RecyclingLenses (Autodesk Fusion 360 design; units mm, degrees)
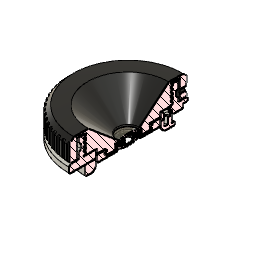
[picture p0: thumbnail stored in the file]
parameter "emount_flange_distance" = 18
parameter "lens_focal_length" = 30
parameter "single_lens_distance" = 12 (= "lens_focal_length - emount_flange_distance")
parameter "double_lens_distance" = 1.6
parameter "thread_clearing" = 0.1 comment "increase value to make more space between threads"
parameter "lens_diameter" = 13.4 (= "13 mm + 0.4 mm")
parameter "lens_height" = 0.8 (= "1 mm - 0.2 mm")
sketch "Sketch1" plane through (0, 0, 0) normal (0, 0, 1) x axis (1, 0, 0)
  line L1 (0, 0) -> (-5.9612, -25.8208)
  line L2 (23.25, 0) -> (0, 0)
  line L3 (-23.25, 0) -> (0, 0)
  line L4 (0, 29.5) -> (0, 23.25)
  line L5 (13.0012, 19.2751) -> (12.1764, 18.0523)
  line L6 (17.004, -15.8565) -> (0, 0)
  line L7 (13.0012, 19.2751) -> (0, 0)
  line L8 (0, 23.25) -> (0, 0)
  line L9 (-16.1304, -16.7443) -> (0, 0)
  line L10 (-7.952, 21.8479) -> (0, 0)
  line L11 (17.004, -15.8565) -> (15.9252, -14.8505)
  line L12 (-14.6317, -18.0686) -> (0, 0)
  line L13 (0, -21.775) -> (0, 0)
  line L14 (-23.1934, 1.6218) -> (0, 0)
  line L15 (-23.1934, 1.6218) -> (-21.722, 1.5189)
  line L16 (-7.952, 21.8479) -> (-7.4475, 20.4618)
  line L17 (29.5, 0) -> (23.25, 0)
  line L18 (-4.7282, -25.5923) -> (-4.9532, -26.5667)
  line L19 (-14.6317, -18.0686) -> (-13.7035, -16.9224)
  line L20 (-5.8487, -25.3336) -> (-6.0737, -26.308)
  line L21 (-15.1071, -15.682) -> (-16.1304, -16.7443)
  line L22 (-7.1942, -26.0493) -> (-6.9693, -25.0749)
  line L23 (23.2358, 0.8114) -> (0, 0)
  line L24 (23.2358, 0.8114) -> (21.7617, 0.7599)
  line L25 (-0.725, -21.7629) -> (-0.725, -16.4841)
  line L26 (0.725, -21.7629) -> (0.725, -16.4841)
  arc A1 centre (0, 0) radius 23.25 clockwise from (-7.952, 21.8479) to (13.0012, 19.2751)
  circle C1 centre (0, 19) radius 0.95
  arc A2 centre (0, 0) radius 23.25 clockwise from (-14.6317, -18.0686) to (-23.1934, 1.6218)
  arc A3 centre (-6.0737, -26.308) radius 1.15 clockwise from (-4.9532, -26.5667) to (-7.1942, -26.0493)
  circle C2 centre (0, 0) radius 23.25
  circle C3 centre (0, 0) radius 21.775
  circle C4 centre (-16.4545, -9.5) radius 0.95
  circle C5 centre (0, 0) radius 16.5
  circle C6 centre (16.4545, -9.5) radius 0.95
  arc A4 centre (-5.8487, -25.3336) radius 1.15 clockwise from (-6.9693, -25.0749) to (-4.7282, -25.5923)
  arc A5 centre (0, 0) radius 23.25 clockwise from (23.2358, 0.8114) to (17.004, -15.8565)
  circle C7 centre (0, 19) radius 1.9
  circle C8 centre (-16.4545, -9.5) radius 1.9
  circle C9 centre (16.4545, -9.5) radius 1.9
  point P11 (0, 0)
  point P21 (0, 0)
  point P12 (0, 0)
  point P17 (0, 0)
  point P16 (-23.1934, 1.6218)
  point P28 (0, 0)
  point P29 (0, 0)
  point P30 (17.004, -15.8565)
  point P38 (0, 0)
  point P39 (13.0012, 19.2751)
  point P6 (-7.952, 21.8479)
  point P7 (0, 0)
  point P43 (23.25, 0)
  point P44 (-21.722, 1.5189)
  point P41 (15.9252, -14.8505)
  point P8 (-23.25, 0)
  point P22 (0, 0)
  point P23 (-14.6317, -18.0686)
  point P24 (-13.7035, -16.9224)
  point P33 (0, 0)
  point P46 (0, 0)
  point P32 (0, 23.25)
  point P25 (12.1764, 18.0523)
  point P45 (-7.4475, 20.4618)
  point P26 (0, 0)
  point P27 (-16.1304, -16.7443)
  point P18 (-15.1071, -15.682)
  point P13 (0, -21.775)
  point P42 (-5.8487, -25.3336)
  point P14 (-5.9612, -25.8208)
  point P35 (-5.9612, -25.8208)
  point P40 (0, 0)
  point P31 (0, 0)
  point P36 (0, 19)
  point P1 (0, 0)
  point P37 (0, 0)
  point P47 (0, 0)
  point P48 (23.2358, 0.8114)
  point P49 (21.7617, 0.7599)
  point P15 (0, 0)
  point P50 (0, 0)
  point P51 (23.25, 0)
  point P52 (16.5, 0)
  point P53 (21.775, 0)
  point P54 (-0.725, -16.4841)
  point P55 (-0.725, -21.7629)
  point P57 (0.725, -21.7629)
  point P56 (0.725, -16.4841)
  point P34 (-6.0737, -26.308)
  coincident P11 P21
  coincident P12 P21
  coincident P17 P21
  coincident P16 C2
  coincident P12 P28
  coincident P11 P29
  coincident P30 C2
  coincident P21 P38
  coincident P39 C2
  coincident P6 C2
  coincident P7 P12
  horizontal L2
  coincident P43 C2
  coincident P44 C3
  coincident P44 L14
  coincident P41 C3
  coincident P41 L6
  horizontal L3
  coincident P8 C2
  coincident P11 P22
  coincident P23 C2
  coincident P24 L12
  coincident P24 C3
  coincident P33 P46
  coincident P32 A1
  coincident P25 C3
  coincident P25 L7
  coincident P45 C3
  coincident P45 L10
  vertical L8
  coincident P12 P26
  coincident P27 A2
  coincident P18 L9
  coincident P18 C3
  coincident P13 C3
  vertical L13
  tangent L18 A4
  tangent L22 A4
  parallel L18 L22
  tangent A3 L22
  tangent A3 L18
  coincident P42 L1
  parallel L1 L20
  coincident P14 P35
  midpoint P35 L20
  coincident P28 P40
  coincident P21 P31
  concentric A1 C5
  coincident P36 L8
  parallel L2 L17
  parallel L4 L8
  coincident P1 P37
  coincident P12 P47
  coincident C2 P48
  coincident C3 P49
  coincident L23 P49
  coincident P15 P50
  coincident P21 P50
  coincident P43 P51
  coincident C5 P52
  coincident L2 P52
  coincident C3 P53
  coincident L2 P53
  coincident C5 P54
  coincident C3 P55
  vertical L25
  coincident C3 P57
  parallel L25 L26
  coincident C5 P56
  concentric C1 C7
  dimension "d214" diameter C3 = 43.55
  dimension "d215" diameter C2 = 46.5 (= "46.20 mm + 0.3 mm")
  dimension "d216" angle L3 L14 = 4
  dimension "d217" angle L3 L12 = 51
  dimension "d219" angle L2 L6 = 43
  dimension "d220" angle L7 L8 = 34
  dimension "d221" angle L8 L10 = 20
  dimension "d223" angle L12 L14 = 55
  dimension "d224" angle L7 L10 = 54
  dimension "d225" distance P23 P27 = 2
  dimension "d226" angle L1 L13 = 13
  dimension "d227" distance P14 P15 = 26.5
  dimension "d228" distance P34 P42 = 1
  dimension "d229" distance L18 L22 = 2.3
  dimension "d231" distance P36 P37 = 19
  dimension "d232" diameter C1 = 1.9
  dimension "d239" angle L2 L23 = 2
  dimension "d285" distance L25 L26 = 1.45 (= "1.2 mm + 0.25 mm")
  dimension "d349" diameter C7 = 3.8
  dimension "d471" diameter C5 = 33
  dimension "d213" C-Pattern1-Angle = 360
sketch "Sketch2" plane through (0, 0, 0) normal (0, 1, 0) x axis (1, 0, 0)
  line L1 (23.25, -1.6) -> (23.25, 0)
  line L2 (21.775, -1.6) -> (23.25, -1.6)
  line L3 (21.775, -5.2) -> (21.775, -1.6)
  line L4 (18, 0) -> (23.25, 0)
  line L5 (16.5, -5.2) -> (16.5, -1.5)
  line L6 (21.775, -5.2) -> (16.5, -5.2)
  line L7 (21.775, -7.2) -> (21.775, -5.2)
  line L8 (20.775, -7.2) -> (21.775, -7.2)
  line L9 (18.775, -5.2) -> (20.775, -7.2)
  line L10 (0, 0) -> (16.5, 0)
  line L11 (16.5, -1.5) -> (18, 0)
  line L12 (18, 0) -> (16.5, 0)
  line L13 (21.775, 0) -> (21.775, -1.6)
  point P11 (18.775, -5.2)
  point P13 (23.25, 0)
  point P15 (21.775, 0)
  point P1 (0, 0)
  point P12 (0, 0)
  point P2 (23.25, 0)
  point P6 (16.5, 0)
  point P14 (16.5, 0)
  point P17 (21.775, 0)
  point P3 (23.25, -1.6)
  point P7 (16.5, -1.5)
  point P16 (18, 0)
  point P5 (21.775, -5.2)
  point P9 (21.775, -7.2)
  point P10 (20.775, -7.2)
  perpendicular L1 L2
  perpendicular L1 L4
  perpendicular L4 L5
  perpendicular L3 L6
  perpendicular L6 L7
  perpendicular L7 L8
  coincident L6 P11
  parallel L4 L10
  perpendicular L2 L3
  horizontal L4
  coincident L1 P13
  coincident L3 P15
  coincident P1 P12
  coincident P2 P13
  coincident P6 L5
  coincident L5 P14
  coincident P15 P17
  dimension "d240" distance P2 P3 = 1.6
  dimension "d243" distance P2 L6 = 5.2
  dimension "d244" angle L11 L12 = 45
  dimension "d245" distance P7 P16 = 1.5
  dimension "d246" angle L6 L9 = 45
  dimension "d247" distance P5 P9 = 2
  dimension "d260" distance P9 P10 = 1
  dimension "d261" distance P9 P11 = 3
revolve "Revolve1" sketch "Sketch2" AlongAngle 360 bodies "EMountFlange"
extrude "Extrude1" add sketch "Sketch1" profile of A1 L5 A2 L11 C3 L15 L16 L19 L21 A4 L24 A5 to an object
fillet "Fillet1" radius 2
extrude "Extrude2" add sketch "Sketch1" profile of A2 C3 L19 L21 to an object offset -0.2
chamfer "Chamfer1" distance 0.4 distance 0.8
sketch "Sketch1" plane through (0, 0, 0) normal (0, 1, 0) x axis (1, 0, 0)
  line L1 (18.6336, 0) -> (16.5, 0)
  line L2 (20.9336, -2.3) -> (18.6336, 0)
  line L3 (22.075, -2.3) -> (20.9336, -2.3)
  line L4 (22.075, 0) -> (22.075, -2.3)
  line L5 (30, 0) -> (22.075, 0)
  line L6 (22.5, -13.5) -> (25, -13.5)
  line L7 (22.5, -4) -> (22.5, -13.5)
  line L8 (16.5, -4) -> (22.5, -4)
  line L9 (16.5, 0) -> (16.5, -4)
  line L10 (30, 0) -> (0, 0)
  line L11 (21.775, -2) -> (21.775, 0)
  line L12 (20.775, -2) -> (21.775, -2)
  line L13 (18.775, 0) -> (20.775, -2)
  line L14 (30, -4) -> (30, 0)
  line L15 (25, -4) -> (30, -4)
  line L16 (25, -13.5) -> (25, -4)
  point P1 (0, 0)
  point P11 (0, 0)
  point P2 (16.5, 0)
  point P12 (21.775, 0)
  point P15 (18.775, 0)
  point P18 (25, -13.5)
  point P5 (22.075, -2.3)
  point P13 (21.775, -2)
  point P14 (20.775, -2)
  point P7 (30, 0)
  point P8 (22.5, -13.5)
  point P10 (16.5, -4)
  point P16 (30, -4)
  horizontal L1
  parallel L1 L3
  perpendicular L3 L4
  perpendicular L4 L5
  perpendicular L3 L7
  perpendicular L7 L8
  perpendicular L1 L9
  coincident P1 P11
  coincident P2 L10
  coincident L10 P12
  perpendicular L10 L11
  perpendicular L11 L12
  coincident L10 P15
  parallel L2 L13
  perpendicular L10 L14
  perpendicular L14 L15
  coincident L6 P18
  perpendicular L6 L16
  coincident P1 L5
  dimension "d262" distance P1 P12 = 21.775 (= "( 43.55 / 2 ) * 1 mm")
  dimension "d263" distance P5 P13 = 0.3
  dimension "d264" angle L10 L13 = 45
  dimension "d265" distance L2 L13 = 0.1
  dimension "d266" distance P12 P13 = 2
  dimension "d267" distance P5 P13 = 0.3
  dimension "d268" distance P13 P14 = 1
  dimension "d269" distance P1 P7 = 30 (= "( 60 / 2 ) * 1 mm")
  dimension "d271" distance P1 P8 = 22.5 (= "( 45 / 2 ) * 1 mm")
  dimension "d272" distance P2 P10 = 4
  dimension "d414" distance P7 P16 = 4
  dimension "d415" distance L5 L6 = 13.5
  dimension "d416" distance P1 P18 = 25 (= "( 50 / 2 ) * 1 mm")
  dimension "d472" distance P1 P10 = 16.5 (= "( 33 / 2 ) * 1 mm")
sketch "Sketch2" plane through (0, 0, 0) normal (0, 0, 1) x axis (1, 0, 0)
  line L1 (0, -26.5) -> (0, 0)
  line L2 (-5.9612, -25.8208) -> (0, 0)
  line L3 (-4.4284, -25.405) -> (-4.7658, -26.8665)
  line L4 (-7.494, -26.2367) -> (-7.1566, -24.7751)
  line L5 (-5.7925, -25.09) -> (-6.1299, -26.5516)
  line L6 (-0.6, -22.0668) -> (-0.6, -18.6239)
  line L7 (0.6, -22.0668) -> (0.6, -18.6239)
  line L8 (0, 30) -> (0, 0)
  circle C1 centre (0, 0) radius 26.5
  arc A1 centre (-5.7925, -25.09) radius 1.4 clockwise from (-7.1566, -24.7751) to (-4.4284, -25.405)
  arc A2 centre (-6.1299, -26.5516) radius 1.4 clockwise from (-4.7658, -26.8665) to (-7.494, -26.2367)
  circle C2 centre (0, 0) radius 22.075
  circle C3 centre (0, 0) radius 18.6336
  arc A3 centre (0, 0) radius 18.6336 clockwise from (0.6, -18.6239) to (-0.6, -18.6239)
  arc A4 centre (0, 0) radius 22.075 clockwise from (0.6, -22.0668) to (-0.6, -22.0668)
  circle C4 centre (0, 0) radius 30
  circle C5 centre (0, 30) radius 2.5
  circle C6 centre (0, 19) radius 1.15
  circle C7 centre (-16.4545, -9.5) radius 1.15
  circle C8 centre (16.4545, -9.5) radius 1.15
  circle C9 centre (0, 19) radius 2.15
  circle C10 centre (-16.4545, -9.5) radius 2.15
  circle C11 centre (16.4545, -9.5) radius 2.15
  point P1 (0, 0)
  point P2 (0, 0)
  point P4 (0, 0)
  point P3 (0, -26.5)
  point P5 (0, 0)
  point P6 (-5.9612, -25.8208)
  point P12 (-5.7925, -25.09)
  point P13 (-5.9612, -25.8208)
  point P14 (0, 0)
  point P16 (-0.6, -18.6239)
  point P17 (-0.6, -22.0668)
  point P18 (0.6, -18.6239)
  point P19 (0.6, -22.0668)
  point P20 (0, 0)
  point P21 (0, 0)
  point P22 (18.6336, 0)
  point P23 (22.075, 0)
  point P24 (30, 0)
  point P26 (0, 0)
  point P27 (0, 30)
  point P28 (0, 30)
  point P29 (0, 19)
  point P11 (-6.1299, -26.5516)
  point P7 (-4.7658, -26.8665)
  point P10 (-7.494, -26.2367)
  point P25 (0, 0)
  coincident P1 P2
  vertical L1
  coincident P1 P4
  coincident P3 C1
  coincident P4 P5
  coincident C1 P6
  tangent L3 A1
  tangent A1 L4
  parallel L3 L4
  tangent L4 A2
  tangent L3 A2
  coincident L2 P12
  parallel L2 L5
  coincident P6 P13
  midpoint L5 P13
  coincident P1 P14
  concentric C2 C3
  coincident C3 P16
  coincident C2 P17
  parallel L1 L6
  coincident C3 P18
  coincident C2 P19
  parallel L1 L7
  coincident P4 P20
  coincident P20 P21
  symmetric L1 L6 L7
  coincident C3 P22
  coincident C2 P23
  concentric A3 C4
  coincident P24 C4
  coincident P1 P26
  coincident C4 P27
  vertical L8
  coincident P27 P28
  coincident L8 P29
  concentric C6 C9
  dimension "d279" distance P5 P6 = 26.5
  dimension "d280" angle L1 L2 = 13
  dimension "d281" distance P11 P12 = 1.5
  dimension "d282" distance P7 P10 = 2.8
  dimension "d290" distance L6 L7 = 1.2
  dimension "d302" diameter C5 = 5
  dimension "d340" diameter C6 = 2.3
  dimension "d343" distance P25 P29 = 19
  dimension "d354" diameter C9 = 4.3
  dimension "d342" C-Pattern1-Angle = 360
revolve "Revolve1" sketch "Sketch1" AlongAngle 360
extrude "Extrude1" cut sketch "Sketch2" profile of L3 A1 L4 A2 along normal blind 2
extrude "Extrude2" add sketch "Sketch2" profile of L6 L7 A3 A4 to an object
joint "Assemble1" alignAngle 0 alignOffsetX 0 alignOffsetY 0 alignOffsetZ 0
extrude "Extrude3" sketch "Sketch1" profile of C3 C5 L25 L26 to an object
chamfer "Chamfer2" distance 0.4
extrude "Extrude3" cut sketch "Sketch2" profile of C5 along normal blind 2
extrude "Extrude4" cut sketch "Sketch2" profile of C6 C7 C8 to an object
chamfer "Chamfer1" distance 0.25
chamfer "Chamfer2" distance 0.3
thread "Thread1"
chamfer "Chamfer4" distance 0.2
sketch "Sketch1" plane through (0, 0, 0) normal (0, 1, 0) x axis (1, 0, 0)
  line L1 (30, -15) -> (5.5, -15)
  line L2 (30, -4.3) -> (30, -15)
  line L3 (26, -13.8) -> (26, -4.3)
  line L4 (22.5, -13.8) -> (26, -13.8)
  line L5 (22.5, -4) -> (22.5, -13.8)
  line L6 (16.5, -4) -> (22.5, -4)
  line L7 (16.5, -13.8) -> (16.5, -4)
  line L8 (10, -13.8) -> (16.5, -13.8)
  line L9 (10, -11.2) -> (10, -13.8)
  line L10 (5.5, -15) -> (5.5, -12)
  line L11 (7.1782, -15) -> (5.5, -13)
  line L12 (16, -13.4) -> (10, -13.4)
  line L13 (16, -9.4) -> (16, -13.4)
  line L14 (27.5, -15) -> (30, -12.5)
  line L15 (6.7, -12) -> (5.5, -12)
  line L16 (6.7, -11.2) -> (6.7, -12)
  line L17 (10, -11.2) -> (6.7, -11.2)
  line L18 (1.5909, -9.4) -> (16, -9.4)
  line L19 (1.5909, -10.2) -> (1.5909, -9.4)
  line L20 (5.5, -10.2) -> (1.5909, -10.2)
  line L21 (5.5, -11.2) -> (5.5, -10.2)
  line L22 (10, -11.2) -> (5.5, -11.2)
  line L23 (30, -4.3) -> (26, -4.3)
  line L24 (30, -5.3) -> (29, -4.3)
  point P9 (16.5, -13.8)
  point P2 (5.5, -15)
  point P12 (5.5, -15)
  point P13 (5.5, -13)
  point P14 (7.1782, -15)
  point P15 (10, -13.4)
  point P18 (30, -12.5)
  point P19 (27.5, -15)
  point P11 (5.5, -12)
  point P28 (29, -4.3)
  point P29 (30, -5.3)
  point P1 (0, 0)
  point P7 (22.5, -4)
  point P22 (10, -11.2)
  point P3 (30, -15)
  point P20 (6.7, -12)
  point P21 (6.7, -11.2)
  point P23 (1.5909, -9.4)
  point P25 (5.5, -10.2)
  point P26 (5.5, -11.2)
  point P24 (1.5909, -10.2)
  point P27 (30, -4.3)
  point P4 (26, -4.3)
  horizontal L1
  perpendicular L1 L2
  perpendicular L3 L4
  perpendicular L5 L6
  perpendicular L6 L7
  perpendicular L5 L8
  coincident L4 P9
  perpendicular L1 L9
  coincident P2 P12
  coincident L10 P13
  coincident L1 P14
  coincident L9 P15
  perpendicular L9 L12
  perpendicular L12 L13
  coincident L2 P18
  coincident L1 P19
  perpendicular L10 L15
  perpendicular L15 L16
  perpendicular L10 L17
  perpendicular L13 L18
  perpendicular L18 L19
  perpendicular L19 L20
  perpendicular L20 L21
  vertical L10
  perpendicular L9 L22
  coincident P11 L21
  perpendicular L3 L23
  perpendicular L2 L23
  coincident L23 P28
  coincident L2 P29
  dimension "d310" distance P1 P7 = 22.5 (= "( 45 / 2 ) * 1 mm")
  dimension "d322" distance P1 P22 = 10
  dimension "d325" angle L10 L11 = 40
  dimension "d326" distance P11 P13 = 1
  dimension "d328" distance L1 L8 = 1.2
  dimension "d329" distance P1 P2 = 5.5 (= "( 13 / 2 ) * 1 mm - 1 mm")
  dimension "d338" distance L8 L12 = 0.4
  dimension "d367" distance P3 P18 = 2.5
  dimension "d368" angle L2 L14 = 45
  dimension "d379" distance P1 P20 = 6.7 (= "lens_diameter / 2")
  dimension "d380" distance P20 P21 = 0.8 (= "lens_height")
  dimension "d381" distance P1 P23 = 1.5909 (= "( ( 35 / 11 ) / 2 ) * 1 mm")
  dimension "d382" distance P25 P26 = 1
  dimension "d383" distance P23 P24 = 0.8
  dimension "d392" distance P2 P11 = 3
  dimension "d393" distance P1 P7 = 4
  dimension "d418" distance P1 L7 = 16.5 (= "( 33 / 2 ) * 1 mm")
  dimension "d419" distance L7 L13 = 0.5
  dimension "d421" distance P1 L2 = 30
  dimension "d477" distance P1 P11 = 12 (= "single_lens_distance")
  dimension "d480" distance P7 P27 = 0.3
  dimension "d481" distance P4 P27 = 4
  dimension "d482" angle L2 L24 = 45
  dimension "d483" distance P27 P29 = 1
sketch "Sketch4" plane through (0, 0, 0) normal (0, 0, 1) x axis (1, 0, 0)
  line L1 (12, -10.583) -> (12, 10.583)
  line L2 (-12, -10.583) -> (-12, 10.583)
  line L3 (0, 16) -> (0, -16)
  circle C1 centre (0, 0) radius 16
  point P1 (0, 0)
  point P2 (0, 0)
  point P3 (16, 0)
  point P4 (12, 10.583)
  point P5 (12, -10.583)
  point P6 (-12, 10.583)
  point P7 (-12, -10.583)
  point P8 (0, -16)
  point P9 (0, 16)
  coincident P1 P2
  coincident C1 P3
  coincident C1 P4
  coincident C1 P5
  vertical L1
  coincident C1 P6
  coincident C1 P7
  parallel L1 L2
  coincident C1 P8
  coincident C1 P9
  vertical L3
  coincident P1 L3
  dimension "d409" distance P4 P6 = 24
sketch "Sketch5" plane through (0, 0, 0) normal (1, 0, 0) x axis (0, -1, 0)
  line L1 (0, -8) -> (0, 0)
  circle C1 centre (0, -8) radius 0.95
  circle C2 centre (0, -8) radius 2.25
  point P1 (0, 0)
  point P4 (0, 0)
  point P3 (0, -8)
  point P5 (0, -8)
  concentric C1 C2
  coincident P1 P4
  coincident P3 P5
  vertical L1
  dimension "d431" diameter C1 = 1.9
  dimension "d432" diameter C2 = 4.5
  dimension "d433" distance P4 P5 = 8
revolve "Revolve1" sketch "Sketch1" AlongAngle 360 bodies "OuterBody"
extrude "Extrude4" sketch "Sketch5" profile of C1 to an object
extrude "Extrude5" sketch "Sketch5" profile of C1 C2 to an object from offset 3
move "Move1" RotateAngle 90
combine "Combine2"
thread "Thread1"
joint "Assemble2" alignAngle 0 alignOffsetX 0 alignOffsetY 0 alignOffsetZ 0
revolve "Revolve2" sketch "Sketch1" AlongAngle 360 bodies "OuterBody_lensscrew"
extrude "Extrude3" sketch "Sketch4" profile of C1 L1 L2 to an object
thread "Thread2"
thread "Thread3"
chamfer "Chamfer1" distance 0.6
chamfer "Chamfer3" distance 0.25
extrude "Extrude4" cut sketch "Sketch1" profile of C1 C4 C6 A4 to an object from offset 2
extrude "Extrude5" sketch "Sketch1" profile of C1 C4 C6 C7 C8 C9 to an object
chamfer "Chamfer4" distance 0.3
chamfer "Chamfer12" distance 1.4
chamfer "Chamfer6" distance 0.2
offset_faces "OffsetFaces1"
offset_faces "OffsetFaces2"
fillet "Fillet1" radius 0.1
offset_faces "OffsetFaces1"
offset_faces "OffsetFaces2"
fillet "Fillet1" radius 0.1
chamfer "Chamfer2" distance 1
chamfer "Chamfer3" distance 0.5
chamfer "Chamfer4" distance 0.25
chamfer "Chamfer5" distance 0.2
chamfer "Chamfer6" distance 0.5
offset_faces "OffsetFaces3"
offset_faces "OffsetFaces4"
offset_faces "OffsetFaces5"
offset_faces "OffsetFaces6"
sketch "Sketch3" plane through (0, 0, 0) normal (0, 0, 1) x axis (1, 0, 0)
  line L1 (29.991, 0.7362) -> (0, 0)
  line L2 (29.991, -0.7362) -> (0, 0)
  line L3 (30, 0) -> (0, 0)
  line L4 (29.991, 0.7362) -> (29.1912, 0.7166)
  line L5 (29.991, -0.7362) -> (29.1912, -0.7166)
  line L6 (30.9627, 1.5211) -> (0, 0)
  line L7 (30.9627, -1.5211) -> (0, 0)
  line L8 (30, 0) -> (5.5, 0)
  circle C1 centre (0, 0) radius 30
  circle C2 centre (0, 0) radius 29.2
  circle C3 centre (0, 0) radius 31
  arc A1 centre (0, 0) radius 29.2 clockwise from (29.1912, 0.7166) to (29.1912, -0.7166)
  point P1 (0, 0)
  point P2 (0, 0)
  point P3 (0, 0)
  point P4 (29.991, 0.7362)
  point P5 (0, 0)
  point P6 (29.991, -0.7362)
  point P8 (0, 0)
  point P13 (29.1912, 0.7166)
  point P11 (0, 0)
  point P12 (29.1912, -0.7166)
  point P14 (30, 0)
  point P15 (0, 0)
  point P16 (30.9627, 1.5211)
  point P17 (0, 0)
  point P18 (30.9627, -1.5211)
  point P21 (30, 0)
  point P20 (30, 0)
  point P9 (30, 0)
  coincident P1 P2
  coincident P2 P3
  coincident C1 P4
  coincident P2 P5
  coincident C1 P6
  coincident P1 P8
  horizontal L3
  symmetric L1 L2 L3
  coincident C2 P13
  coincident L1 P13
  coincident P1 P11
  coincident L2 P12
  coincident C1 P14
  coincident P2 P15
  coincident C3 P16
  coincident P1 P17
  coincident C3 P18
  symmetric L6 L7 L8
  horizontal L8
  coincident P14 P21
  coincident P14 P20
  coincident P9 P21
  dimension "d395" = -0.8
  dimension "d396" angle L1 L2 = 2.812 (= "( 360 / 128 ) * 1 deg")
  dimension "d397" = 1
  dimension "d406" angle L6 L7 = 5.625 (= "( 360 / 64 ) * 1 deg")
revolve "Revolve3" sketch "Sketch1" AlongAngle 360
extrude "Extrude2" new body sketch "Sketch3" profile of C1 L1 L2 C3 A1 L6 L7 L8 to an object
fillet "Fillet2" radius 0.25
circular_pattern "C-Pattern1" countU 64 TotalAngle 360
combine "Combine1"
chamfer "Chamfer8" distance 0.25
chamfer "Chamfer7" distance 0.4
chamfer "Chamfer8" distance 1
fillet "Fillet2" radius 0.5
chamfer "Chamfer9" distance 0.4
chamfer "Chamfer10" distance 0.6
chamfer "Chamfer9" distance 0.3 distance 0.3
sketch "Sketch3" plane through (0, 0, 0) normal (0, 0, 1) x axis (1, 0, 0)
  line L1 (30, 0) -> (0, 0)
  line L2 (28.1908, -10.2606) -> (0, 0)
  circle C1 centre (0, 0) radius 30
  point P1 (0, 0)
  point P2 (0, 0)
  point P3 (0, 0)
  point P4 (30, 0)
  point P5 (0, 0)
  point P6 (28.1908, -10.2606)
  coincident P1 P2
  coincident P1 P3
  coincident C1 P4
  horizontal L1
  coincident P1 P5
  coincident C1 P6
  dimension "d441" angle L1 L2 = 20
  dimension "d442" diameter C1 = 60
sketch "Sketch4" plane through (0, 0, 0) normal (0, 1, 0) x axis (1, 0, 0)
  line L1 (157.0796, -4) -> (0, -4)
  line L2 (157.0796, -13.5) -> (157.0796, -4)
  line L3 (0, -13.5) -> (157.0796, -13.5)
  line L4 (0, -4) -> (0, -13.5)
  line L5 (141.3583, -10.8499) -> (-0.0134, -9.0499)
  line L6 (0.0134, -6.9501) -> (141.385, -8.7501)
  line L7 (141.3717, -9.8) -> (0, -8)
  line L8 (-1.05, -6.8365) -> (-1.05, -9.1367)
  line L9 (142.4217, -8.6633) -> (-1.05, -6.8365)
  line L10 (142.4217, -10.9635) -> (-1.05, -9.1367)
  line L11 (142.4217, -10.9635) -> (142.4217, -8.6633)
  arc A1 centre (141.3717, -9.8) radius 1.05 clockwise from (141.385, -8.7501) to (141.3583, -10.8499)
  arc A2 centre (0, -8) radius 1.05 clockwise from (-0.0134, -9.0499) to (0.0134, -6.9501)
  point P10 (0, -8)
  point P12 (25, -13.5)
  point P13 (25, -4)
  point P14 (0, 0)
  point P4 (157.0796, -13.5)
  point P5 (0, -13.5)
  point P2 (0, -4)
  point P11 (141.3717, -9.8)
  horizontal L1
  vertical L2
  horizontal L3
  vertical L4
  tangent L5 A1
  tangent A1 L6
  parallel L5 L6
  tangent L6 A2
  tangent L5 A2
  coincident L4 P10
  coincident L3 P12
  coincident L1 P13
  coincident L4 P14
  tangent A1 L11
  vertical L11
  parallel L5 L10
  vertical L8
  tangent A2 L8
  dimension "d451" distance P4 P5 = 157.0796 (= "( PI * 50 ) * 1 mm")
  dimension "d453" distance L5 L6 = 2.1
  dimension "d456" distance P2 P10 = 4
  dimension "d457" distance P10 P11 = 1.8 (= "( 2 * 0.9 ) * 1 mm")
  dimension "d458" distance L2 P11 = 15.708 (= "( ( PI * 50 ) * 0.1 ) * 1 mm")
  dimension "d463" distance L5 L10 = 0.1
emboss "Emboss1" sketch "Sketch4" Depth -1.2 Horizontal Distance 0 Vertical Distance 0 Rotation Angle 0
chamfer "Chamfer11" distance 0.8 distance 1.2
fillet "Fillet3" radius 0.5
base_feature "Base Feature"
joint "Assemble3" alignAngle 0 alignOffsetX 0 alignOffsetY 0 alignOffsetZ 0
chamfer "Chamfer13" distance 0.2
chamfer "Chamfer5" distance 0.1
sketch "Sketch1" plane through (0, 0, 0) normal (0, 1, 0) x axis (1, 0, 0)
  line L1 (30, -15) -> (5.5, -15)
  line L2 (30, -4.3) -> (30, -15)
  line L3 (26, -13.8) -> (26, -4.3)
  line L4 (22.5, -4) -> (22.5, -13.8)
  line L5 (16, -4) -> (22.5, -4)
  line L6 (16, -1.8) -> (16, -4)
  line L7 (12, -1.8) -> (16, -1.8)
  line L8 (12, 1.2) -> (12, -1.8)
  line L9 (5.5, -15) -> (5.5, -1.6)
  line L10 (20.2777, -15) -> (5.5, -2.6)
  line L11 (16, -1.4) -> (12, -1.4)
  line L12 (16, 2.2) -> (16, -1.4)
  line L13 (27.5, -15) -> (30, -12.5)
  line L14 (6.7, -1.6) -> (5.5, -1.6)
  line L15 (6.7, 1.2) -> (6.7, -1.6)
  line L16 (12, 1.2) -> (6.7, 1.2)
  line L17 (5.5, 2.2) -> (16, 2.2)
  line L18 (5.5, 1.2) -> (5.5, 2.2)
  line L19 (12, 1.2) -> (5.5, 1.2)
  line L20 (30, -4.3) -> (26, -4.3)
  line L21 (30, -5.3) -> (29, -4.3)
  line L22 (22.5, -13.8) -> (26, -13.8)
  line L23 (6.4, 0.4) -> (1.5909, 0.4)
  line L24 (6.4, -0.6) -> (6.4, 0.4)
  line L25 (1.5909, -0.6) -> (6.4, -0.6)
  line L26 (1.5909, 0.4) -> (1.5909, -0.6)
  point P2 (5.5, -15)
  point P10 (5.5, -15)
  point P11 (5.5, -2.6)
  point P12 (20.2777, -15)
  point P13 (12, -1.4)
  point P16 (30, -12.5)
  point P17 (27.5, -15)
  point P9 (5.5, -1.6)
  point P24 (29, -4.3)
  point P25 (30, -5.3)
  point P7 (16, -1.8)
  point P1 (0, 0)
  point P5 (22.5, -4)
  point P20 (12, 1.2)
  point P3 (30, -15)
  point P18 (6.7, -1.6)
  point P19 (6.7, 1.2)
  point P23 (30, -4.3)
  point P4 (26, -4.3)
  point P8 (12, -1.8)
  point P21 (5.5, 2.2)
  point P22 (5.5, 1.2)
  point P28 (1.5909, 0.4)
  point P31 (1.5909, -0.6)
  point P30 (6.4, -0.6)
  horizontal L1
  perpendicular L1 L2
  perpendicular L4 L5
  perpendicular L5 L6
  perpendicular L4 L7
  perpendicular L1 L8
  coincident P2 P10
  coincident L9 P11
  coincident L1 P12
  coincident L8 P13
  perpendicular L8 L11
  perpendicular L11 L12
  coincident L2 P16
  coincident L1 P17
  perpendicular L9 L14
  perpendicular L14 L15
  perpendicular L9 L16
  perpendicular L12 L17
  vertical L9
  perpendicular L8 L19
  coincident P9 L18
  perpendicular L3 L20
  perpendicular L2 L20
  coincident L20 P24
  coincident L2 P25
  perpendicular L3 L22
  perpendicular L17 L18
  horizontal L23
  vertical L24
  horizontal L25
  vertical L26
  coincident P7 L12
  dimension "d310_1" distance P1 P5 = 22.5 (= "( 45 / 2 ) * 1 mm")
  dimension "d322_1" distance P1 P20 = 12
  dimension "d325_1" angle L9 L10 = 50
  dimension "d326_1" distance P9 P11 = 1
  dimension "d329_1" distance P1 P2 = 5.5 (= "( 13 / 2 ) * 1 mm - 1 mm")
  dimension "d338_1" distance L7 L11 = 0.4
  dimension "d367_1" distance P3 P16 = 2.5
  dimension "d368_1" angle L2 L13 = 45
  dimension "d379_1" distance P1 P18 = 6.7 (= "lens_diameter / 2")
  dimension "d380_1" distance P18 P19 = 2.8 (= "2 mm + lens_height")
  dimension "d393_1" distance P1 P5 = 4
  dimension "d418_1" distance P1 L6 = 16 (= "( 33 / 2 ) * 1 mm - 0.5 mm")
  dimension "d421_1" distance P1 L2 = 30
  dimension "d480_1" distance P5 P23 = 0.3
  dimension "d481_1" distance P4 P23 = 4
  dimension "d482_1" angle L2 L21 = 45
  dimension "d483_1" distance P23 P25 = 1
  dimension "d484" distance L1 L22 = 1.2
  dimension "d485" distance P8 P20 = 3
  dimension "d486" distance P1 P2 = 15
  dimension "d487" distance P21 P22 = 1
  dimension "d488" distance P1 P9 = 1.6 (= "double_lens_distance")
  dimension "d491" distance L15 L24 = 0.3
  dimension "d492" distance P28 P31 = 1
  dimension "d493" distance P18 P30 = 1
  dimension "d494" distance P1 P28 = 1.5909 (= "( 17.5 / 11 ) * 1 mm")
sketch "Sketch4" plane through (0, 0, 0) normal (0, 0, 1) x axis (1, 0, 0)
  line L1 (13, -9.3274) -> (13, 9.3274)
  line L2 (-13, -9.3274) -> (-13, 9.3274)
  line L3 (0, 16) -> (0, -16)
  circle C1 centre (0, 0) radius 16
  point P1 (0, 0)
  point P2 (0, 0)
  point P3 (16, 0)
  point P4 (13, 9.3274)
  point P5 (13, -9.3274)
  point P6 (-13, 9.3274)
  point P7 (-13, -9.3274)
  point P8 (0, -16)
  point P9 (0, 16)
  coincident P1 P2
  coincident C1 P3
  coincident C1 P4
  coincident C1 P5
  vertical L1
  coincident C1 P6
  coincident C1 P7
  parallel L1 L2
  coincident C1 P8
  coincident C1 P9
  vertical L3
  symmetric L1 L2 L3
  coincident P1 L3
  dimension "d409_1" distance P4 P6 = 26
sketch "Sketch5" plane through (0, 0, 0) normal (1, 0, 0) x axis (0, -1, 0)
  line L1 (0, -8) -> (0, 0)
  circle C1 centre (0, -8) radius 0.95
  circle C2 centre (0, -8) radius 2.25
  point P1 (0, 0)
  point P4 (0, 0)
  point P3 (0, -8)
  point P5 (0, -8)
  concentric C1 C2
  coincident P1 P4
  coincident P3 P5
  vertical L1
  dimension "d431_1" diameter C1 = 1.9
  dimension "d432_1" diameter C2 = 4.5
  dimension "d433_1" distance P4 P5 = 8
revolve "Revolve1" sketch "Sketch1" AlongAngle 360 named "d314_1" bodies "OuterBody"
extrude "Extrude4" sketch "Sketch5" profile of C1 to an object
extrude "Extrude5" sketch "Sketch5" profile of C1 C2 to an object from offset 3 named "d437_1"
move "Move1" RotateAngle 90 named "d461_1"
combine "Combine2"
thread "Thread1"
position "Position1"
joint_origin "JointOrigin5"
revolve "Revolve2" sketch "Sketch1" AlongAngle 360 named "d339_1" bodies "OuterBody_lensscrew"
extrude "Extrude3" sketch "Sketch4" profile of C1 L1 L2 to an object
thread "Thread2"
thread "Thread3"
offset_faces "OffsetFaces1"
offset_faces "OffsetFaces2"
fillet "Fillet1" radius 0.1 named "d377_1"
chamfer "Chamfer2" distance 0.3 named "d378_1"
chamfer "Chamfer3" distance 0.5 named "d384_1"
chamfer "Chamfer5" distance 0.2 named "d386_1"
offset_faces "OffsetFaces3"
offset_faces "OffsetFaces4"
offset_faces "OffsetFaces5"
offset_faces "OffsetFaces6"
sketch "Sketch3" plane through (0, 0, 0) normal (0, 0, 1) x axis (1, 0, 0)
  line L1 (29.991, 0.7362) -> (0, 0)
  line L2 (29.991, -0.7362) -> (0, 0)
  line L3 (30, 0) -> (0, 0)
  line L4 (29.991, 0.7362) -> (29.1912, 0.7166)
  line L5 (29.991, -0.7362) -> (29.1912, -0.7166)
  line L6 (30.9627, 1.5211) -> (0, 0)
  line L7 (30.9627, -1.5211) -> (0, 0)
  line L8 (30, 0) -> (5.5, 0)
  circle C1 centre (0, 0) radius 30
  circle C2 centre (0, 0) radius 29.2
  circle C3 centre (0, 0) radius 31
  arc A1 centre (0, 0) radius 29.2 clockwise from (29.1912, 0.7166) to (29.1912, -0.7166)
  point P1 (0, 0)
  point P2 (0, 0)
  point P3 (0, 0)
  point P4 (29.991, 0.7362)
  point P5 (0, 0)
  point P6 (29.991, -0.7362)
  point P8 (0, 0)
  point P13 (29.1912, 0.7166)
  point P11 (0, 0)
  point P12 (29.1912, -0.7166)
  point P14 (30, 0)
  point P15 (0, 0)
  point P16 (30.9627, 1.5211)
  point P17 (0, 0)
  point P18 (30.9627, -1.5211)
  point P21 (30, 0)
  point P20 (30, 0)
  point P9 (30, 0)
  coincident P1 P2
  coincident P2 P3
  coincident C1 P4
  coincident P2 P5
  coincident C1 P6
  coincident P1 P8
  horizontal L3
  symmetric L1 L2 L3
  coincident C2 P13
  coincident L1 P13
  coincident P1 P11
  coincident L2 P12
  coincident C1 P14
  coincident P2 P15
  coincident C3 P16
  coincident P1 P17
  coincident C3 P18
  symmetric L6 L7 L8
  horizontal L8
  coincident P14 P21
  coincident P14 P20
  coincident P9 P21
  dimension "d395_1" = -0.8
  dimension "d396_1" angle L1 L2 = 2.812 (= "( 360 / 128 ) * 1 deg")
  dimension "d397_1" = 1
  dimension "d406_1" angle L6 L7 = 5.625 (= "( 360 / 64 ) * 1 deg")
revolve "Revolve3" sketch "Sketch1" AlongAngle 360 named "d430_1"
extrude "Extrude2" new body sketch "Sketch3" profile of C1 L1 L2 C3 A1 L6 L7 L8 to an object
fillet "Fillet2" radius 0.25 named "d408_1"
circular_pattern "C-Pattern1" countU 64 named "d402_1" TotalAngle 360 named "d403_1"
combine "Combine1"
chamfer "Chamfer8" distance 0.25 named "d413_1"
chamfer "Chamfer9" distance 0.3 named "d440_1" distance 0.3 named "d462_1"
chamfer "Chamfer10" distance 0.2
chamfer "Chamfer11" distance 0.2
revolve "Revolve4" sketch "Sketch1" AlongAngle 360 bodies "OuterBody_aperture"
chamfer "Chamfer12" distance 0.2
sketch "Sketch1" plane through (0, 0, 0) normal (1, 0, 0) x axis (0, 1, 0)
  curve K1 (7, -1.4) -> (-7, -1.4)
  curve K2 (0, 2.2591) -> (0, -5.0591)
  curve K3 (6.8, -1.9) -> (-6.8, -1.9)
  curve K4 (0, 1.2646) -> (0, -5.0646)
  line L1 (0, -1.4) -> (0, 0)
  line L2 (6.5, 0) -> (5, 0)
  line L3 (6.5, 1) -> (6.5, 0)
  line L4 (5, 1) -> (6.5, 1)
  line L5 (5, 0) -> (5, 1)
  line L6 (0, 1.2646) -> (0, 2.2591)
  closed curve K5 centre (0, -1.4)
  closed curve K6 centre (0, -1.9)
  point P3 (-7, -1.4)
  point P4 (7, -1.4)
  point P5 (0, -5.0591)
  point P6 (0, 2.2591)
  point P8 (-6.8, -1.9)
  point P9 (6.8, -1.9)
  point P10 (0, -5.0646)
  point P11 (0, 1.2646)
  point P1 (0, 0)
  point P12 (0, 0)
  point P2 (0, -1.4)
  point P13 (0, -1.4)
  point P7 (0, -1.9)
  point P15 (6.5, 0)
  point P16 (6.5, 1)
  point P14 (5, 0)
  coincident K5 P3
  coincident K5 P4
  coincident K5 P5
  coincident K5 P6
  horizontal K1
  coincident K6 P8
  coincident K6 P9
  coincident K6 P10
  coincident K6 P11
  perpendicular K2 K3
  coincident P1 P12
  coincident P2 P13
  vertical L1
  coincident P7 L1
  horizontal L2
  vertical L3
  horizontal L4
  vertical L5
  coincident P1 L2
  parallel K2 L6
  dimension "d502" distance P2 P7 = 0.5
  dimension "d503" distance P15 P16 = 1
  dimension "d504" distance P1 P14 = 5
  dimension "d505" distance P1 P16 = 6.5 (= "( 13 / 2 ) * 1 mm")
revolve "Revolve1" sketch "Sketch1" AlongAngle 360
joint "Assemble4" alignAngle 0 alignOffsetX 0 alignOffsetY 0 alignOffsetZ 0
copy_paste "CopyPaste1"
copy_paste "CopyPaste2"
joint "Assemble5" alignAngle 0 alignOffsetX 0 alignOffsetY 0 alignOffsetZ 0
joint "Assemble6" alignAngle 0 alignOffsetX 0 alignOffsetY 0 alignOffsetZ 0
joint_origin "JointOrigin6"
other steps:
create_component "CreateComponent4"
create_component "CreateComponent5"
joint_origin "JointOrigin1"
joint_origin "JointOrigin1"
create_component "CreateComponent6"
joint_origin "JointOrigin5"
joint_origin "JointOrigin6"
create_component "CreateComponent7"
joint_origin "JointOrigin1"
joint_origin "JointOrigin6"
create_component "CreateComponent8"
create_component "CreateComponent9"
joint_origin "JointOrigin2"
joint_origin "JointOrigin8"
joint_origin "JointOrigin3"
joint_origin "JointOrigin7"
joint_origin "JointOrigin4"
joint_origin "JointOrigin8"
named bodies: "EMountFlange", "InnerBody", "OuterBody", "OuterBody_lensscrew", "OuterBody_aperture"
